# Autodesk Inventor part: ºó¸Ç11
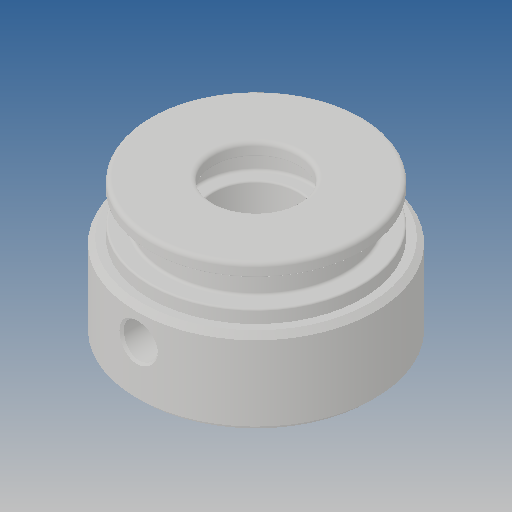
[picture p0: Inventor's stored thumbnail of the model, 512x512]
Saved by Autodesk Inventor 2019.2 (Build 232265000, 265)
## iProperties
Created: 2013-09
Part Number: ºó¸Ç11
Material: Ogólny
Document SubType Name: Modeling
Designer: CADENGINEERING4
Density: 1 g/cm^3
Appearance: Domyślna
Author: CADENGINEERING4
Revision Number: ÈÎºÎ
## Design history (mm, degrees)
feature "µ¹½Ç3"
node "Bryła1"
